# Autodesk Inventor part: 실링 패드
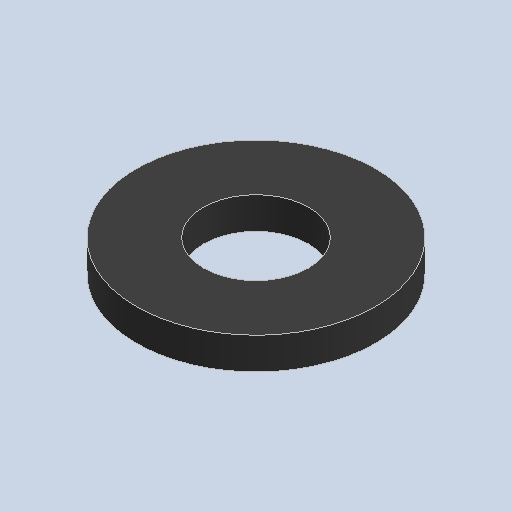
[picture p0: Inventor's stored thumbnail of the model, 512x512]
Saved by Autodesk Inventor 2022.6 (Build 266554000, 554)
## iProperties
Created: 2024-09
Part Number: 실링 패드
Material: 고무
Document SubType Name: Modeling
Designer: Class 001
Density: 0.93 g/cm^3
Appearance: 기본값
Author: jhkim
Sending System: Autodesk Inventor 2025
Preprocessor: ST-DEVELOPER v20
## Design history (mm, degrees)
feature "솔리드1"
node "솔리드2"
